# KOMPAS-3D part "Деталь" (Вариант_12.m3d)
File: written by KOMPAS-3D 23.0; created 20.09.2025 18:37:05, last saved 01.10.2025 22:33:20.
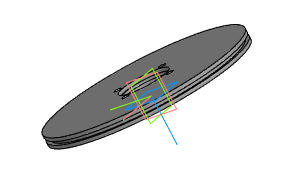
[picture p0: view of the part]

Document properties: Автор: ssafo; Полное имя файла: C:\Users\ssafo\OneDrive\Desktop\ЦД_Грант\Решенные варианты\Вариант_12.m3d

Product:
- Part/product: Деталь
    Масса: 6.403445
    Форматы листов документа: A4

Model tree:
1. Эскиз:1
2. Элемент вращения:1
     Угол 1 = 360
3. Эскиз:2  (with: Элемент вращения:1)
4. Элемент выдавливания:1
     Расстояние 1 = 5
5. Эскиз:3  (with: Элемент выдавливания:1)
6. Элемент выдавливания:2
     Расстояние 2 = 25
7. Массив по концентрической сетке:1  (with: Элемент выдавливания:2, Эскиз:3, Элемент выдавливания:1)  (4 pattern instances)
     Шаг 2 = 360
8. Фаска:1  (with: Элемент выдавливания:2)
     Угол = 45; Длина 1 = 1; Длина 2 = 1
9. Эскиз:4  (with: Элемент вращения:1)
10. Элемент выдавливания:3
     Расстояние 2 = 25
11. Эскиз:5  (with: Элемент вращения:1)
12. Элемент выдавливания:4
     Расстояние 2 = 5
13. Скругление:2  (with: Элемент выдавливания:4)
     Радиус = 3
